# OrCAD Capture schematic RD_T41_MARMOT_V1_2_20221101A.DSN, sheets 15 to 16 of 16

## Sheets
15 PAGE15_UART_RTC_BOOT_EFUSE_KEY: size A3
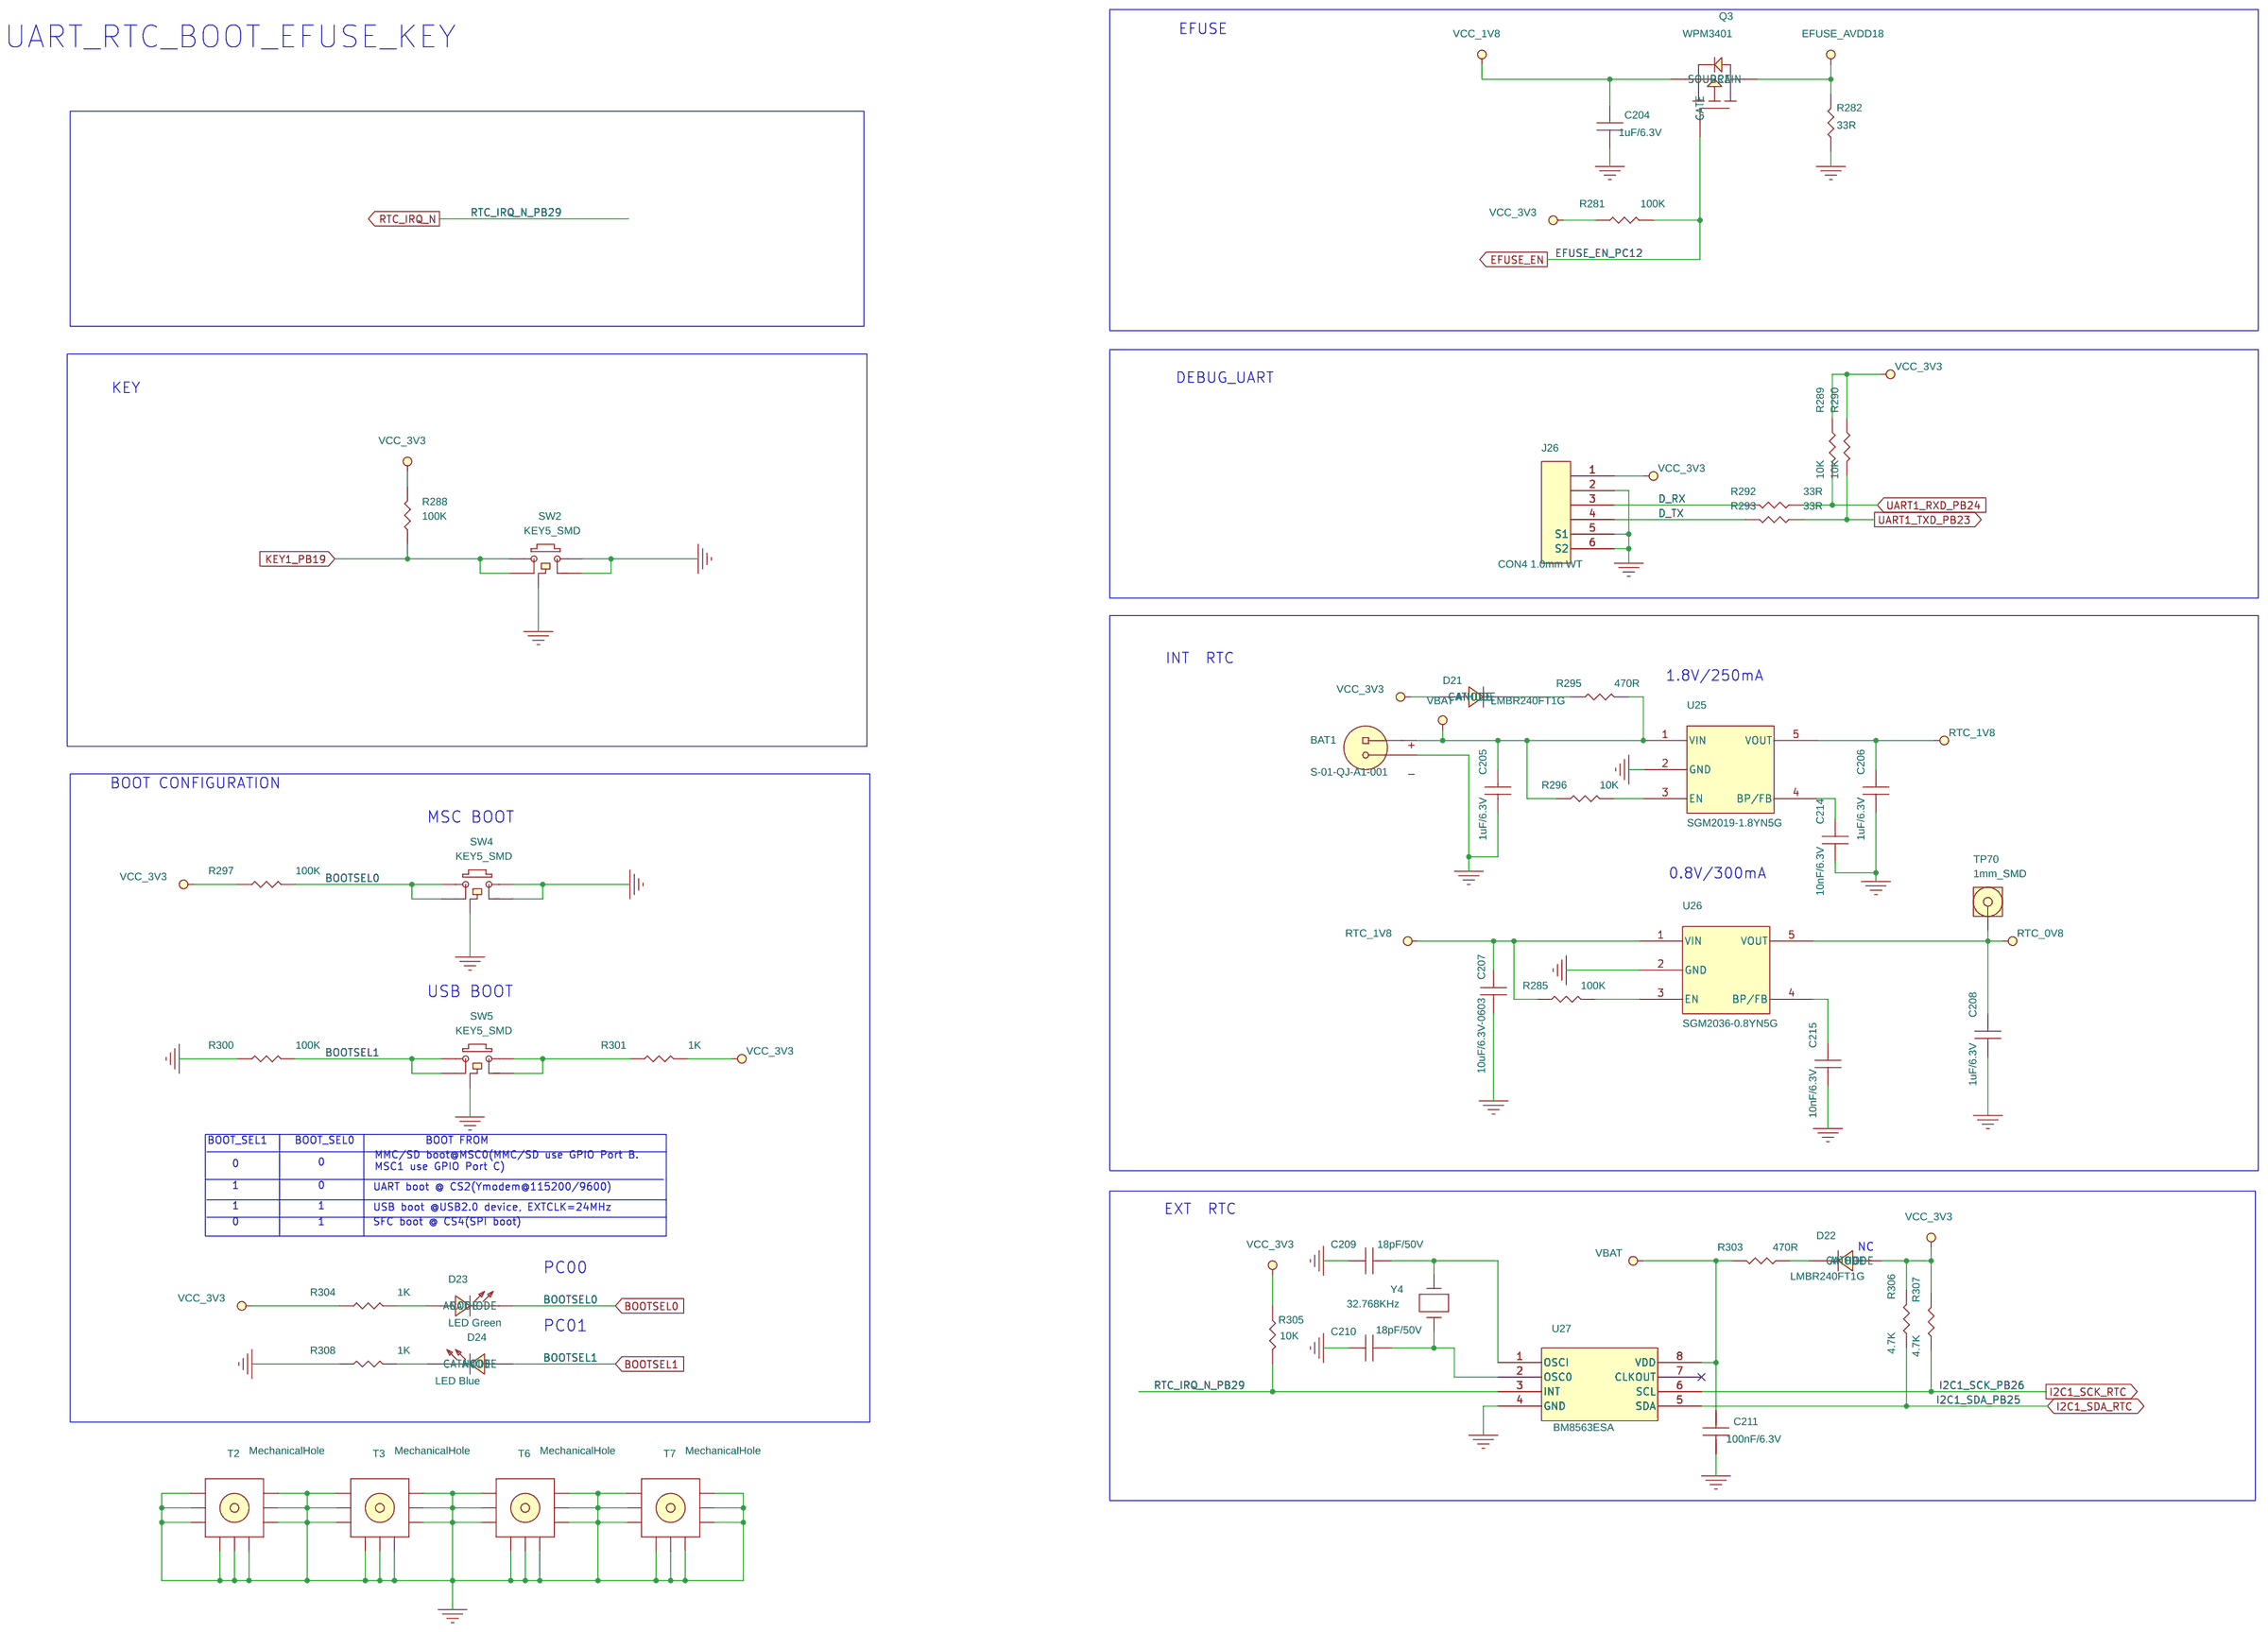
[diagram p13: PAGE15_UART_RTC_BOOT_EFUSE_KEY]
16 PAGE16_REVISION-HISTORY
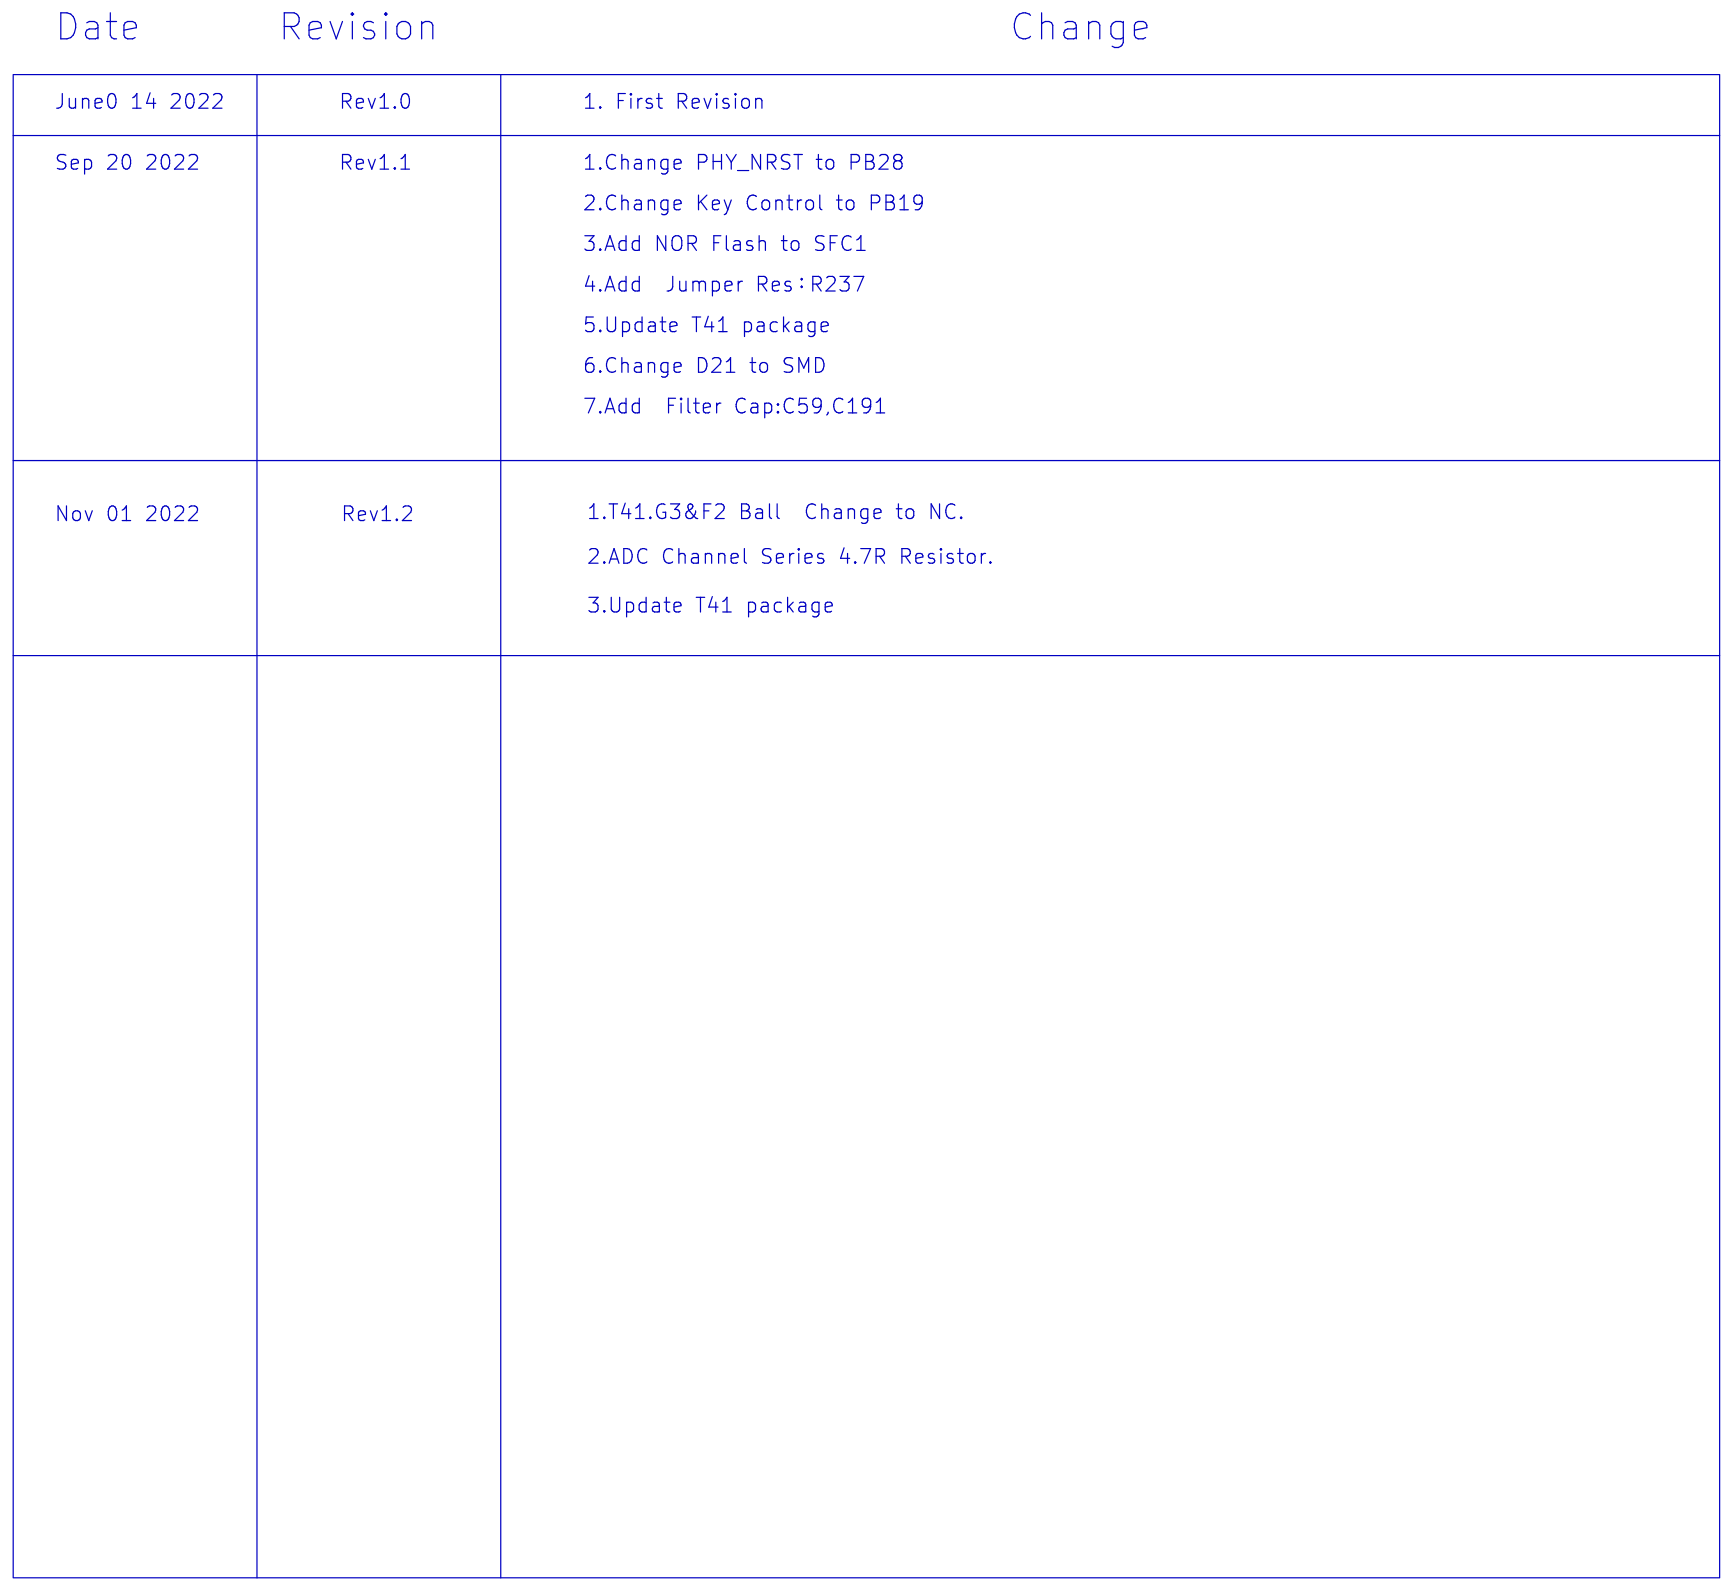
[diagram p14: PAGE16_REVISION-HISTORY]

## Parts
BAT1  S-01-QJ-A1-001  [BAT2_S-01-QJ-A1-001]
C204  1uF/6.3V  [C0402]
C205  1uF/6.3V  [C0402]
C206  1uF/6.3V  [C0402]
C207  10uF/6.3V-0603  [C0603]
C208  1uF/6.3V  [C0402]
C209  18pF/50V  [C0402]
C210  18pF/50V  [C0402]
C211  100nF/6.3V  [C0402]
C214  10nF/6.3V  [C0402]
C215  10nF/6.3V  [C0402]
D21  LMBR240FT1G  [SOD123]
D22  LMBR240FT1G  [SOD123]
D23  LED Green  [D0603_LED]
D24  LED Blue  [D0603_LED]
J26  CON4 1.0mm WT  [CON4-1D0-WT]
Q3  WPM3401  [SOT23]
R281  100K  [R0402]
R282  33R  [R0402]
R285  100K  [R0402]
R288  100K  [R0402]
R289  10K  [R0402]
R290  10K  [R0402]
R292  33R  [R0402]
R293  33R  [R0402]
R295  470R  [R0402]
R296  10K  [R0402]
R297  100K  [R0402]
R300  100K  [R0402]
R301  1K  [R0402]
R303  470R  [R0402]
R304  1K  [R0402]
R305  10K  [R0402]
R306  4.7K  [R0402]
R307  4.7K  [R0402]
R308  1K  [R0402]
SW2  KEY5_SMD  [SW5_SMD]
SW4  KEY5_SMD  [SW5_SMD]
SW5  KEY5_SMD  [SW5_SMD]
T2  MechanicalHole  [MHOLE_5D5P3D2H]
T3  MechanicalHole  [MHOLE_5D5P3D2H]
T6  MechanicalHole  [MHOLE_5D5P3D2H]
T7  MechanicalHole  [MHOLE_5D5P3D2H]
TP70  1mm_SMD  [TEST_SMD]
U25  SGM2019-1.8YN5G  [SOT23-5]
U26  SGM2036-0.8YN5G  [SOT23-5]
U27  BM8563ESA  [SOP8_1D27_BM8563]
Y4  32.768KHz  [CRY_3D2X1D5]

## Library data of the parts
BAT1 = CR2032_SOCKET: CR2032 2pin卧式纽扣电池底座 φ22.1mm H=8.7mm; Part Number: 10.0056.00; Part Type: 纽扣电池; Datasheet: CR2032电池卧式底座_C70376.pdf
C204-C206 C208 = CAP: Capacitor-1uF,+/-10%,X7R,6.3V-0402; Part Number: 02.0076.00; Part Type: 0402表贴普通电容; 供应商: Murata; 规格型号1: GRM155R70J105KA12; 联系人: 谢苏云; 手机: 15900554174; 邮箱: susan.xie@murata.com
C207 = CAP: Capacitor-10uF,+/-20%,X5R,6.3V-0603; Part Number: 02.0026.00; Part Type: 0603表贴普通电容; 供应商: Murata; 规格型号1: GRM188R60J106ME47D; 联系人: 谢苏云; 手机: 15900554174; 邮箱: susan.xie@murata.com
C209 C210 = CAP: Capacitor-18pF,+/-2%,C0G,50V-0402; Part Number: 02.0049.00; Part Type: 0402表贴普通电容; 供应商: 国巨 / Murata; 规格型号1: CC0402GRNPO9BN180 / GRM1555C1H180GA01D; 联系人: 谢苏云; 手机: 15900554174; 邮箱: susan.xie@murata.com
C211 = CAP: Capacitor-100nF,+/-10%,X7R,6.3V-0402; Part Number: 02.0075.00; Part Type: 0402表贴普通电容; 供应商: Murata; 规格型号1: GRM155R70J104KA01D; 联系人: 谢苏云; 手机: 15900554174; 邮箱: susan.xie@murata.com
C214 C215 = CAP: Capacitor-10nF,+/-10%,X7R,6.3V-0402; Part Number: 02.0075.00; Part Type: 0402表贴普通电容; 供应商: Murata; 规格型号1: GRM155R70J102KA01D; 联系人: 谢苏云; 手机: 15900554174; 邮箱: susan.xie@murata.com
D21 D22 = DIODE: LRC LMBR240FT1G Schottky Barrier Rectifiers Reverse Voltage 40V 2A; Part Number: 09.0012.00; Part Type: 二极管; Datasheet: LMBR240FT1G.pdf
D23 = LED_1: Part Number: 09.0005.00; Part Type: 发光二极管; 规格型号1: 0603贴片绿灯; Datasheet: 0603_LED.PDF
D24 = LED_1: Part Number: 09.0004.00; Part Type: 发光二极管; 规格型号1: 0603贴片蓝灯; Datasheet: 0603_LED.PDF
J26 = CON_4X1: HOLY 1.0mm Pitch 4P WT SMD Connector; Part Number: 04.0004.00; Part Type: 1.0mm卧贴连接器; 供应商: 深圳宏利电子; 规格型号1: 1mm卧贴4P插座; 联系人: 谢素平; 手机: 16717558767; Datasheet: 1.0mmA 卧贴.pdf
Q3 = P_MOS: WILL WPM3401 P-Channel MOSFET; Part Number: 09.0008.00; Part Type: MOS管; 供应商: Will; 联系人: 安志鹏; 手机: 18321800431; 邮箱: an.zhipeng@sh-willsemi.com; Datasheet: WPM340_datasheet.pdf
R281 R285 R288 R297 R300 = RES: Resistor-100K,+/-5%,1/16W-0402; Part Number: 01.0041.00; Part Type: 0402表贴普通电阻; 供应商: 厚声; 规格型号1: 0402WGJ0104TCE
R282 R292 R293 = RES: Resistor-33R,+/-5%,1/16W-0402; Part Number: 01.0005.00; Part Type: 0402表贴普通电阻; 供应商: 厚声; 规格型号1: 0402WGJ0330TCE
R289 R290 R296 R305 = RES: Resistor-10K,+/-5%,1/16W-0402; Part Number: 01.0023.00; Part Type: 0402表贴普通电阻; 供应商: 厚声; 规格型号1: 0402WGJ0103TCE
R295 R303 = RES: Resistor-470R,+/-5%,1/16W-0402; Part Number: 01.0114.00; Part Type: 0402表贴普通电阻; 供应商: 厚声; 规格型号1: 0402WGJ0471TCE
R301 R304 R308 = RES: Resistor-1K,+/-5%,1/16W-0402; Part Number: 01.0014.00; Part Type: 0402表贴普通电阻; 供应商: 厚声; 规格型号1: 0402WGJ0102TCE
R306 R307 = RES: Resistor-4.7K,+/-5%,1/16W-0402; ID: 23; Part Number: 01.0019.00; Part Type: 0402表贴普通电阻; 供应商: 厚声; 供应商1: Eyang; 规格型号1: 0402WGJ0472TCE; 联系人1: 何俊; 手机1: 18317187178; 邮箱1: hejunxs@szeyang.com
SW2 SW4 SW5 = SW_5: PUSHBUTTON 10mmX6mm 5Pin; Part Number: 04.1002.00; Part Type: 按键; 规格型号1: 6*6*3.1-5P轻触按键
T2 T3 T6 T7 = MHOLE2: MechanicalHole φ5.5mm Drill 3.2mm With 8 GND Vias; Part Number: AB.0002.00
TP70 = TP: SMD Test Point φ1mm; Part Number: AA.0001.00; Part Type: Test Point
U25 = SGM2019: SGMICRO SGM2019-1.8 300mA Input 2.5V~5.5V LDO Regulator; Part Number: 05.0009.00; Part Type: LDO; 供应商: SGMICRO; 规格型号1: SGM2019-1.8YN5G/TR; 联系人: 王哲; 手机: 18406666893; 邮箱: jayden_wang@sg-micro.com; Datasheet: SGM2019 Series.pdf
U26 = SGM2036: SGMICRO SGM2036-0.8 300mA Input 1.6V~5.5V RF LDO Regulator; Part Number: 05.0018.00; Part Type: LDO; 供应商: SGMICRO; 规格型号1: SGM2036-0.8YN5G/TR; 联系人: 王哲; 手机: 18406666893; 邮箱: jayden_wang@sg-micro.com; Datasheet: SGM2036 REV.A.4_20151123.pdf
U27 = BM8563: 上海贝岭 BM8563 高精度低功耗实时时钟芯片; Part Number: 06.0141.00; Part Type: RTC芯片; 供应商: 上海贝岭; Datasheet: BM8563_V1.1_cn.pdf
Y4 = XTAL_P2: MICRO Crystal CM7V-T1A Crystal 32.768KHz 12.5pF; Part Number: 08.0016.00; Part Type: Crystal; 供应商: MicroCrystal; 规格型号1: CM7V-T1A; 联系人: 郑蓓蓓; 手机: 13482156565; 邮箱: Sherry.Zheng@cn.swatchgroup.com; Datasheet: CM7V-T1A.pdf

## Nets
GND: BAT1.2 C204.2 C205.2 C206.2 C207.2 C208.2 C209.1 C210.1 C211.2 C214.2 C215.2 J26.2 J26.5(S1) J26.6(S2) R282.1 R300.1 R308.1 SW2.1 SW2.2 SW2.5 SW4.1 SW4.2 SW4.5 SW5.2 T2.1 T2.2 T2.3 T2.4 T2.5 T2.6 T2.7 T2.8 T2.9 T3.1 T3.2 T3.3 T3.4 T3.5 T3.6 T3.7 T3.8 T3.9 T6.1 T6.2 T6.3 T6.4 T6.5 T6.6 T6.7 T6.8 T6.9 T7.1 T7.2 T7.3 T7.4 T7.5 T7.6 T7.7 T7.8 T7.9 U25.2(GND) U26.2(GND) U27.4(GND) ; also on sheet 3 4 5 6 7 8 9 10 11 12 13 14
VBAT: BAT1.1 C205.1 C211.1 R295.2 R296.1 R303.2 U25.1(VIN) U27.8(VDD)
VCC_1V8: C204.1 Q3.2(SOURCE) ; also on sheet 3 5
VCC_3V3: D21.1(ANODE) D22.1(ANODE) J26.1 R281.1 R288.2 R289.1 R290.1 R297.1 R301.2 R304.1 R305.2 R306.2 R307.2 ; also on sheet 3 5 7 8 9 10 11 12 13 14
BOOTSEL0: D23.2(CATHODE) R297.2 SW4.3 SW4.4 ; also on sheet 5
BOOTSEL1: D24.1(ANODE) R300.2 SW5.3 SW5.4 ; also on sheet 5
D_RX: J26.3 R292.1
D_TX: J26.4 R293.1
EFUSE_AVDD18: Q3.3(DRAIN) R282.2 ; also on sheet 5
EFUSE_EN: Q3.1(GATE) R281.2 ; also on sheet 7
I2C1_SCK_RTC: R307.1 U27.6(SCL) ; also on sheet 6
I2C1_SDA_RTC: R306.1 U27.5(SDA) ; also on sheet 6
KEY1_PB19: R288.1 SW2.3 SW2.4 ; also on sheet 6
RTC_0V8: C208.1 TP70.1 U26.5(VOUT) ; also on sheet 5
RTC_1V8: C206.1 C207.1 R285.1 U25.5(VOUT) U26.1(VIN) ; also on sheet 5
RTC_IRQ_N: R305.1 U27.3(INT) ; also on sheet 6
UART1_RXD_PB24: R289.2 R292.2 ; also on sheet 6
UART1_TXD_PB23: R290.2 R293.2 ; also on sheet 6
N17110008: D23.1(ANODE) R304.2
N17269254: R301.1 SW5.1 SW5.5
N17275101: D24.2(CATHODE) R308.2
N17641417: D21.2(CATHODE) R295.1
N17641433: R296.2 U25.3(EN)
N17700250: D22.2(CATHODE) R303.1
N17700350: C209.2 U27.1(OSCI) Y4.2
N17700378: C210.2 U27.2(OSC0) Y4.1
N17861413: C214.1 U25.4(BP/FB)
N17864164: R285.2 U26.3(EN)
N17864213: C215.1 U26.4(BP/FB)

Not connected (* = marked no-connect by the designer): U27 7(CLKOUT)*

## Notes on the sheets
sheet 15
- UART_RTC_BOOT_EFUSE_KEY
- EFUSE
- DEBUG_UART
- KEY
- INT  RTC
- 1.8V/250mA
- BOOT CONFIGURATION
- MSC BOOT
- 0.8V/300mA
- USB BOOT
- BOOT_SEL1
- BOOT_SEL0
- BOOT FROM
- 0
- 0
- MMC/SD boot@MSC0(MMC/SD use GPIO Port B.
  MSC1 use GPIO Port C)
- 1
- 0
- UART boot @ CS2(Ymodem@115200/9600)
- 1
- 1
- USB boot @USB2.0 device, EXTCLK=24MHz
- EXT  RTC
- 0
- 1
- SFC boot @ CS4(SPI boot)
- NC
- PC00
- PC01
sheet 16
- Date
- Revision
- Change
- June0 14 2022
- Rev1.0
- 1. First Revision
- Sep 20 2022
- Rev1.1
- 1.Change PHY_NRST to PB28
- 2.Change Key Control to PB19
- 3.Add NOR Flash to SFC1
- 4.Add  Jumper Res：R237
- 5.Update T41 package
- 6.Change D21 to SMD
- 7.Add  Filter Cap:C59,C191
- Nov 01 2022
- Rev1.2
- 1.T41.G3&F2 Ball  Change to NC.
- 2.ADC Channel Series 4.7R Resistor.
- 3.Update T41 package
